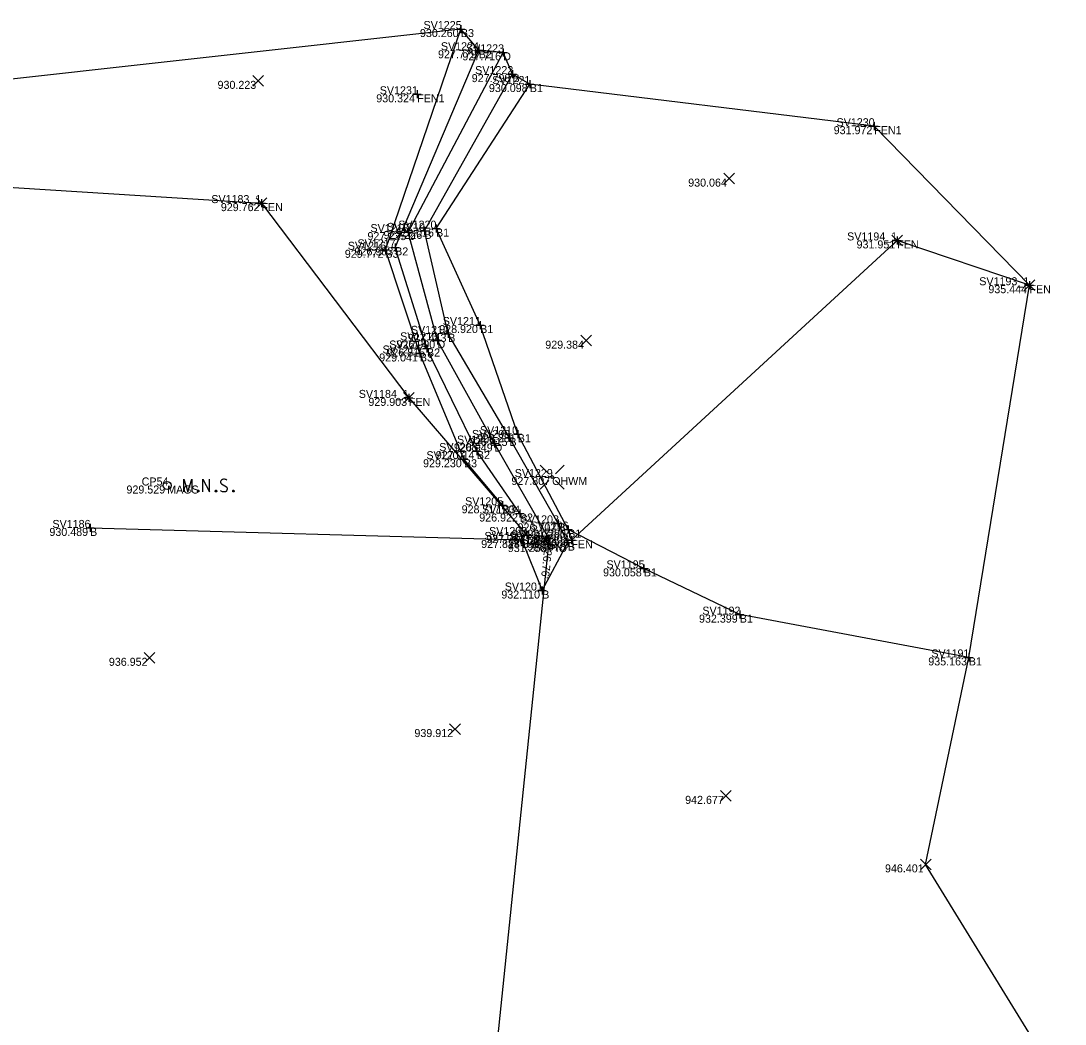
# Model space of a CAD drawing. Extents: x 2065431 to 2068157, y 709104 to 709719.
# Drawn here: x 2067248 to 2067378.4, y 709504.2 to 709629.4 of the extents above; entities that cross this region are included whole.
import ezdxf

# ---------------------------------------------------------------- set-up
doc = ezdxf.new("R2010")
doc.units = 0
for name, color, linetype in [('_CIVIL_CONSTRUCTION', 7, 'Continuous'), ('DR_X_Storm_Sewer', 7, 'Continuous'), ('DT_X_Terrain_Boundary', 7, 'Continuous'), ('RD_X_Fence', 7, 'Continuous'), ('RS_Raster1', 7, 'Continuous'), ('RW_X_CL_100_Bearings', 7, 'Continuous'), ('RW_X_CL_100_Curve_Data', 7, 'Continuous'), ('RW_X_CL_100_Stations', 7, 'Continuous'), ('RW_X_Fee_WL', 7, 'Continuous'), ('SC_Scratch1', 7, 'Continuous'), ('SV_X_Break_Lines', 7, 'Continuous'), ('SV_X_Mon_Cells_Found', 7, 'Continuous'), ('SV_X_Text_Elevation', 7, 'Continuous'), ('SV_X_Text_Name', 7, 'Continuous')]:
    doc.layers.add(name, color=color, linetype=linetype)

msp = doc.modelspace()

# ---------------------------------------------------------------- linework, layer by layer
at = {"layer": '_CIVIL_CONSTRUCTION'}
for p, q in [((2067313.41, 709564.11), (2067314.41, 709564.11)), ((2067313.91, 709564.61), (2067313.91, 709563.61)), ((2067313.91, 709564.11), (2067313.91, 709564.11))]:
    msp.add_line(p, q, dxfattribs=at)
at = {"layer": 'DR_X_Storm_Sewer'}
msp.add_line((2067313.91, 709564.11), (2067272.26, 709162.87), dxfattribs=at)
at = {"layer": 'DT_X_Terrain_Boundary'}
msp.add_lwpolyline([(2067560.73, 709418.79), (2067495.34, 709436.29), (2067456.65, 709439.38), (2067410.67, 709443.42), (2067361.02, 709524.1), (2067366.41, 709549.95), (2067373.99, 709596.43), (2067354.6, 709616.29), (2067311.55, 709621.56), (2067309.4, 709622.8), (2067308.24, 709625.52), (2067305.17, 709625.78), (2067302.95, 709628.43), (2067239.24, 709621.32), (2067197.78, 709611.01), (2067153.08, 709612.99), (2067144.2, 709539.81), (2067080.32, 709510.92)], dxfattribs=at)
at = {"layer": 'RD_X_Fence'}
for points in [[(2067153.08, 709612.99), (2067197.68, 709610.98), (2067232.51, 709609.56), (2067278.02, 709606.69), (2067296.45, 709582.36), (2067311.18, 709565.23)], [(2067373.99, 709596.43), (2067357.47, 709602.03), (2067316.75, 709564.58)]]:
    msp.add_lwpolyline(points, dxfattribs=at)
at = {"layer": 'RS_Raster1'}
for p, q in [((2067302.45, 709628.43), (2067303.45, 709628.43)), ((2067302.95, 709628.93), (2067302.95, 709627.93)), ((2067302.95, 709628.43), (2067302.95, 709628.43)), ((2067304.67, 709625.78), (2067305.67, 709625.78)), ((2067305.17, 709626.28), (2067305.17, 709625.28)), ((2067305.17, 709625.78), (2067305.17, 709625.78)), ((2067307.74, 709625.52), (2067308.74, 709625.52)), ((2067308.24, 709626.02), (2067308.24, 709625.02)), ((2067308.24, 709625.52), (2067308.24, 709625.52)), ((2067308.9, 709622.8), (2067309.9, 709622.8)), ((2067309.4, 709623.3), (2067309.4, 709622.3)), ((2067309.4, 709622.8), (2067309.4, 709622.8)), ((2067311.05, 709621.56), (2067312.05, 709621.56)), ((2067311.55, 709622.06), (2067311.55, 709621.06)), ((2067311.55, 709621.56), (2067311.55, 709621.56)), ((2067296.99, 709620.28), (2067297.99, 709620.28)), ((2067297.49, 709620.78), (2067297.49, 709619.78)), ((2067297.49, 709620.28), (2067297.49, 709620.28)), ((2067354.1, 709616.29), (2067355.1, 709616.29)), ((2067354.6, 709616.79), (2067354.6, 709615.79)), ((2067354.6, 709616.29), (2067354.6, 709616.29)), ((2067278.02, 709607.19), (2067278.02, 709606.19)), ((2067277.52, 709606.69), (2067278.52, 709606.69)), ((2067278.02, 709606.69), (2067278.02, 709606.69)), ((2067295.84, 709603.07), (2067296.84, 709603.07)), ((2067296.34, 709603.57), (2067296.34, 709602.57)), ((2067296.34, 709603.07), (2067296.34, 709603.07)), ((2067297.89, 709603.22), (2067298.89, 709603.22)), ((2067298.39, 709603.72), (2067298.39, 709602.72)), ((2067298.39, 709603.22), (2067298.39, 709603.22)), ((2067299.34, 709603.5), (2067300.34, 709603.5)), ((2067299.84, 709604), (2067299.84, 709603)), ((2067299.84, 709603.5), (2067299.84, 709603.5)), ((2067294.73, 709601.66), (2067294.73, 709600.66)), ((2067356.97, 709602.03), (2067357.97, 709602.03)), ((2067357.47, 709602.53), (2067357.47, 709601.53)), ((2067357.47, 709602.03), (2067357.47, 709602.03)), ((2067293.02, 709600.86), (2067294.02, 709600.86)), ((2067293.52, 709601.36), (2067293.52, 709600.36)), ((2067293.52, 709600.86), (2067293.52, 709600.86)), ((2067294.23, 709601.16), (2067295.23, 709601.16)), ((2067294.73, 709601.16), (2067294.73, 709601.16)), ((2067373.49, 709596.43), (2067374.49, 709596.43)), ((2067373.99, 709596.93), (2067373.99, 709595.93)), ((2067373.99, 709596.43), (2067373.99, 709596.43)), ((2067304.85, 709591.46), (2067305.85, 709591.46)), ((2067305.35, 709591.96), (2067305.35, 709590.96)), ((2067305.35, 709591.46), (2067305.35, 709591.46)), ((2067300.02, 709590.05), (2067300.02, 709589.05)), ((2067300.87, 709590.36), (2067301.87, 709590.36)), ((2067301.37, 709590.86), (2067301.37, 709589.86)), ((2067301.37, 709590.36), (2067301.37, 709590.36)), ((2067298.71, 709589.03), (2067298.71, 709588.03)), ((2067299.52, 709589.55), (2067300.52, 709589.55)), ((2067300.02, 709589.55), (2067300.02, 709589.55)), ((2067297.32, 709587.91), (2067298.32, 709587.91)), ((2067297.82, 709588.41), (2067297.82, 709587.41)), ((2067297.82, 709587.91), (2067297.82, 709587.91)), ((2067298.21, 709588.53), (2067299.21, 709588.53)), ((2067298.71, 709588.53), (2067298.71, 709588.53)), ((2067295.95, 709582.36), (2067296.95, 709582.36)), ((2067296.45, 709582.86), (2067296.45, 709581.86)), ((2067296.45, 709582.36), (2067296.45, 709582.36)), ((2067310.05, 709578.33), (2067310.05, 709577.33)), ((2067307.16, 709577.16), (2067307.16, 709576.16)), ((2067308.51, 709577.36), (2067309.51, 709577.36)), ((2067309.01, 709577.86), (2067309.01, 709576.86)), ((2067309.01, 709577.36), (2067309.01, 709577.36)), ((2067309.55, 709577.83), (2067310.55, 709577.83)), ((2067310.05, 709577.83), (2067310.05, 709577.83)), ((2067304.44, 709575.72), (2067305.44, 709575.72)), ((2067304.94, 709576.22), (2067304.94, 709575.22)), ((2067304.94, 709575.72), (2067304.94, 709575.72)), ((2067306.66, 709576.66), (2067307.66, 709576.66)), ((2067307.16, 709576.66), (2067307.16, 709576.66)), ((2067302.83, 709574.7), (2067303.83, 709574.7)), ((2067303.33, 709575.2), (2067303.33, 709574.2)), ((2067303.33, 709574.7), (2067303.33, 709574.7)), ((2067308.14, 709569.45), (2067308.14, 709568.45)), ((2067307.64, 709568.95), (2067308.64, 709568.95)), ((2067308.14, 709568.95), (2067308.14, 709568.95)), ((2067309.81, 709567.92), (2067310.81, 709567.92)), ((2067310.31, 709568.42), (2067310.31, 709567.42)), ((2067310.31, 709567.92), (2067310.31, 709567.92)), ((2067256.61, 709566.62), (2067256.61, 709565.62)), ((2067314.6, 709566.69), (2067315.6, 709566.69)), ((2067315.1, 709567.19), (2067315.1, 709566.19)), ((2067315.1, 709566.69), (2067315.1, 709566.69)), ((2067316.35, 709566.41), (2067316.35, 709565.41)), ((2067256.11, 709566.12), (2067257.11, 709566.12)), ((2067256.61, 709566.12), (2067256.61, 709566.12)), ((2067310.58, 709565.12), (2067310.58, 709564.12)), ((2067310.68, 709565.23), (2067311.68, 709565.23)), ((2067311.18, 709565.73), (2067311.18, 709564.73)), ((2067311.18, 709565.23), (2067311.18, 709565.23)), ((2067313.95, 709565.3), (2067313.95, 709564.3)), ((2067315.85, 709565.91), (2067316.85, 709565.91)), ((2067316.35, 709565.91), (2067316.35, 709565.91)), ((2067316.75, 709565.08), (2067316.75, 709564.08)), ((2067310.08, 709564.62), (2067311.08, 709564.62)), ((2067310.58, 709564.62), (2067310.58, 709564.62)), ((2067313.45, 709564.8), (2067314.45, 709564.8)), ((2067313.95, 709564.8), (2067313.95, 709564.8)), ((2067315.82, 709564.29), (2067316.82, 709564.29)), ((2067316.25, 709564.58), (2067317.25, 709564.58)), ((2067316.32, 709564.79), (2067316.32, 709563.79)), ((2067316.32, 709564.29), (2067316.32, 709564.29)), ((2067316.75, 709564.58), (2067316.75, 709564.58)), ((2067325.81, 709561.57), (2067325.81, 709560.57)), ((2067325.31, 709561.07), (2067326.31, 709561.07)), ((2067325.81, 709561.07), (2067325.81, 709561.07)), ((2067313.11, 709558.8), (2067313.11, 709557.8)), ((2067312.61, 709558.3), (2067313.61, 709558.3)), ((2067313.11, 709558.3), (2067313.11, 709558.3)), ((2067337.29, 709555.29), (2067338.29, 709555.29)), ((2067337.79, 709555.79), (2067337.79, 709554.79)), ((2067337.79, 709555.29), (2067337.79, 709555.29)), ((2067365.91, 709549.95), (2067366.91, 709549.95)), ((2067366.41, 709550.45), (2067366.41, 709549.45)), ((2067366.41, 709549.95), (2067366.41, 709549.95))]:
    msp.add_line(p, q, dxfattribs=at)
at = {"layer": 'RW_X_CL_100_Bearings'}
for p, q in [((2067276.94, 709621.3), (2067278.27, 709622.63)), ((2067276.94, 709622.63), (2067278.27, 709621.3)), ((2067335.81, 709609.08), (2067337.14, 709610.42)), ((2067335.81, 709610.42), (2067337.14, 709609.08)), ((2067277.36, 709606.03), (2067278.69, 709607.36)), ((2067277.36, 709607.36), (2067278.69, 709606.03)), ((2067356.81, 709601.36), (2067358.14, 709602.69)), ((2067356.81, 709602.69), (2067358.14, 709601.36)), ((2067373.32, 709595.77), (2067374.65, 709597.1)), ((2067373.32, 709597.1), (2067374.65, 709595.77)), ((2067317.94, 709588.85), (2067319.27, 709590.18)), ((2067317.94, 709590.18), (2067319.27, 709588.85)), ((2067295.78, 709581.69), (2067297.12, 709583.03)), ((2067295.78, 709583.03), (2067297.12, 709581.69)), ((2067263.36, 709549.23), (2067264.7, 709550.56)), ((2067263.36, 709550.56), (2067264.7, 709549.23)), ((2067301.54, 709540.33), (2067302.88, 709541.67)), ((2067301.54, 709541.67), (2067302.88, 709540.33)), ((2067335.4, 709531.99), (2067336.73, 709533.33)), ((2067335.4, 709533.33), (2067336.73, 709531.99)), ((2067360.36, 709523.43), (2067361.69, 709524.77)), ((2067360.36, 709524.77), (2067361.69, 709523.43))]:
    msp.add_line(p, q, dxfattribs=at)
at = {"layer": 'RW_X_CL_100_Curve_Data'}
for points in [[(2067268.34, 709570.62), (2067268.34, 709572.22), (2067268.84, 709570.62), (2067269.33, 709572.22), (2067269.33, 709570.62)], [(2067270.71, 709570.62), (2067270.71, 709572.22), (2067271.53, 709570.62), (2067271.53, 709572.22)], [(2067273.68, 709572.1), (2067273.66, 709572.13), (2067273.63, 709572.15), (2067273.53, 709572.19), (2067273.41, 709572.22), (2067273.32, 709572.22), (2067273.29, 709572.22), (2067273.14, 709572.18), (2067273.02, 709572.1), (2067272.94, 709572), (2067272.92, 709571.9), (2067272.92, 709571.83), (2067272.94, 709571.73), (2067273.03, 709571.64), (2067273.64, 709571.26), (2067273.69, 709571.21), (2067273.72, 709571.16), (2067273.74, 709571.08), (2067273.74, 709571.01), (2067273.73, 709570.93), (2067273.72, 709570.88), (2067273.69, 709570.82), (2067273.67, 709570.77), (2067273.65, 709570.73), (2067273.62, 709570.69), (2067273.58, 709570.67), (2067273.54, 709570.64), (2067273.51, 709570.63), (2067273.41, 709570.62), (2067273.25, 709570.62), (2067273.15, 709570.64), (2067273.01, 709570.73), (2067272.92, 709570.81)], [(2067270.1, 709570.83), (2067270.16, 709570.83), (2067270.19, 709570.81), (2067270.22, 709570.76), (2067270.22, 709570.69), (2067270.19, 709570.64), (2067270.16, 709570.62), (2067270.1, 709570.62), (2067270.07, 709570.64), (2067270.04, 709570.69), (2067270.04, 709570.76), (2067270.07, 709570.81), (2067270.1, 709570.83)], [(2067272.32, 709570.83), (2067272.37, 709570.83), (2067272.4, 709570.81), (2067272.44, 709570.76), (2067272.44, 709570.69), (2067272.4, 709570.64), (2067272.37, 709570.62), (2067272.32, 709570.62), (2067272.28, 709570.64), (2067272.25, 709570.69), (2067272.25, 709570.76), (2067272.28, 709570.81), (2067272.32, 709570.83)], [(2067274.5, 709570.83), (2067274.55, 709570.83), (2067274.59, 709570.81), (2067274.62, 709570.76), (2067274.62, 709570.69), (2067274.59, 709570.64), (2067274.55, 709570.62), (2067274.5, 709570.62), (2067274.47, 709570.64), (2067274.43, 709570.69), (2067274.43, 709570.76), (2067274.47, 709570.81), (2067274.5, 709570.83)]]:
    msp.add_lwpolyline(points, dxfattribs=at)
msp.add_circle((2067266.25, 709571.42), 0.497, dxfattribs=at)
at = {"layer": 'RW_X_CL_100_Stations'}
for p, q in [((2067312.84, 709573.98), (2067313.94, 709572.89)), ((2067314.77, 709572.89), (2067315.86, 709573.98)), ((2067312.84, 709570.96), (2067313.94, 709572.06)), ((2067314.77, 709572.06), (2067315.86, 709570.96))]:
    msp.add_line(p, q, dxfattribs=at)
msp.add_circle((2067314.35, 709572.48), 0.17, dxfattribs=at)
at = {"layer": 'RW_X_Fee_WL'}
msp.add_lwpolyline([(2067313.95, 709564.8), (2067307.16, 709576.66), (2067300.02, 709589.55), (2067296.34, 709603.07), (2067308.24, 709625.52)], dxfattribs=at)
at = {"layer": 'SV_X_Break_Lines'}
for points in [[(2067308.14, 709568.95), (2067303.33, 709574.7), (2067297.82, 709587.91), (2067293.52, 709600.86), (2067302.95, 709628.43)], [(2067310.31, 709567.92), (2067304.94, 709575.72), (2067298.71, 709588.53), (2067294.73, 709601.16), (2067305.17, 709625.78)], [(2067256.61, 709566.12), (2067310.58, 709564.62), (2067313.11, 709558.3), (2067316.32, 709564.29), (2067315.1, 709566.69), (2067309.01, 709577.36), (2067301.37, 709590.36), (2067298.39, 709603.22), (2067309.4, 709622.8)], [(2067366.41, 709549.95), (2067337.79, 709555.29), (2067325.81, 709561.07), (2067316.35, 709565.91), (2067310.05, 709577.83), (2067305.35, 709591.46), (2067299.84, 709603.5), (2067311.55, 709621.56)]]:
    msp.add_lwpolyline(points, dxfattribs=at)

# ---------------------------------------------------------------- texts
at = {"layer": 'SC_Scratch1'}
msp.add_text("926.76'", height=1, rotation=264.0747, dxfattribs=at).set_placement((2067313.41, 709564.16))
at = {"layer": 'SV_X_Mon_Cells_Found'}
for s, p in [('SV1225', (2067298.28, 709628.43)), ('SV1224', (2067300.45, 709625.78)), ('SV1223', (2067303.58, 709625.52)), ('SV1222', (2067304.73, 709622.8)), ('SV1221', (2067306.87, 709621.56)), ('SV1231', (2067292.81, 709620.28)), ('SV1230', (2067349.89, 709616.29)), ('SV1183_1', (2067271.76, 709606.69)), ('SV1219', (2067293.71, 709603.22)), ('SV1220', (2067295.13, 709603.5)), ('SV1218', (2067291.65, 709603.07)), ('SV1194_1', (2067351.21, 709602.03)), ('SV1216', (2067288.82, 709600.86)), ('SV1217', (2067290.03, 709601.16)), ('SV1193_1', (2067367.72, 709596.43)), ('SV1211', (2067300.68, 709591.46)), ('SV1212', (2067296.7, 709590.36)), ('SV1213', (2067295.36, 709589.55)), ('SV1215', (2067293.16, 709587.91)), ('SV1214', (2067293.99, 709588.53)), ('SV1184_1', (2067290.19, 709582.36)), ('SV1209', (2067304.33, 709577.36)), ('SV1210', (2067305.33, 709577.83)), ('SV1206', (2067302.46, 709576.66)), ('SV1207', (2067298.64, 709574.7)), ('SV1208', (2067300.24, 709575.72)), ('SV1229', (2067309.67, 709572.48)), ('CP54', (2067263.06, 709571.42)), ('SV1205', (2067303.47, 709568.95)), ('SV1204', (2067305.59, 709567.92)), ('SV1203', (2067310.44, 709566.69)), ('SV1186', (2067251.91, 709566.12)), ('SV1196', (2067311.65, 709565.91)), ('SV1199', (2067305.89, 709564.62)), ('SV1200', (2067306.47, 709565.23)), ('SV1198', (2067309.21, 709564.11)), ('SV1197', (2067309.26, 709564.8)), ('SV1202', (2067311.65, 709564.29)), ('SV7000', (2067312.03, 709564.58)), ('SV1195', (2067321.14, 709561.07)), ('SV1201', (2067308.43, 709558.3)), ('SV1192', (2067333.12, 709555.29)), ('SV1191', (2067361.73, 709549.95))]:
    msp.add_text(s, height=1, dxfattribs=at).set_placement(p)
at = {"layer": 'SV_X_Text_Elevation'}
for s, p in [('B3', (2067302.95, 709627.43)), ('B2', (2067305.17, 709624.78)), ('D', (2067308.24, 709624.52)), ('B', (2067309.4, 709621.8)), ('B1', (2067311.55, 709620.56)), ('FEN1', (2067297.49, 709619.28)), ('FEN1', (2067354.6, 709615.3)), ('FEN', (2067278.02, 709605.69)), ('D', (2067296.34, 709602.07)), ('B', (2067298.39, 709602.22)), ('B1', (2067299.84, 709602.5)), ('FEN', (2067357.47, 709601.03)), ('B3', (2067293.52, 709599.86)), ('B2', (2067294.73, 709600.16)), ('FEN', (2067373.99, 709595.44)), ('B1', (2067305.35, 709590.46)), ('B', (2067301.37, 709589.36)), ('B2', (2067298.71, 709587.53)), ('D', (2067300.02, 709588.55)), ('B3', (2067297.82, 709586.91)), ('FEN', (2067296.45, 709581.36)), ('B', (2067309.01, 709576.36)), ('B1', (2067310.05, 709576.83)), ('B2', (2067304.94, 709574.72)), ('D', (2067307.16, 709575.66)), ('B3', (2067303.33, 709573.7)), ('OHWM', (2067314.35, 709571.48)), ('MAGS', (2067266.25, 709570.42)), ('B3', (2067308.14, 709567.95)), ('B2', (2067310.31, 709566.92)), ('B', (2067315.1, 709565.69)), ('B', (2067256.61, 709565.12)), ('FEN', (2067311.18, 709564.23)), ('B1', (2067316.35, 709564.91)), ('B', (2067310.58, 709563.62)), ('PIO', (2067313.91, 709563.11)), ('D', (2067313.95, 709563.8)), ('B', (2067316.32, 709563.29)), ('FEN', (2067316.75, 709563.58)), ('B1', (2067325.81, 709560.07)), ('B', (2067313.11, 709557.3)), ('B1', (2067337.79, 709554.29)), ('B1', (2067366.41, 709548.95))]:
    msp.add_text(s, height=1, dxfattribs=at).set_placement(p)
at = {"layer": 'SV_X_Text_Name'}
for s, p in [('930.260', (2067297.83, 709627.43)), ('927.779', (2067300.09, 709624.78)), ('927.716', (2067303.13, 709624.52)), ('927.798', (2067304.3, 709621.8)), ('930.223', (2067272.54, 709620.96)), ('930.098', (2067306.45, 709620.56)), ('930.324', (2067292.37, 709619.28)), ('931.972', (2067349.53, 709615.3)), ('930.064', (2067331.35, 709608.75)), ('929.762', (2067272.95, 709605.69)), ('929.762', (2067272.95, 709605.69)), ('927.225', (2067291.27, 709602.07)), ('927.226', (2067293.28, 709602.22)), ('929.016', (2067294.74, 709602.5)), ('931.951', (2067352.39, 709601.03)), ('931.951', (2067352.39, 709601.03)), ('929.772', (2067288.44, 709599.86)), ('926.983', (2067289.66, 709600.16)), ('935.444', (2067368.86, 709595.44)), ('935.444', (2067368.86, 709595.44)), ('928.920', (2067300.24, 709590.46)), ('927.443', (2067296.31, 709589.36)), ('926.815', (2067293.64, 709587.53)), ('926.900', (2067294.9, 709588.55)), ('929.384', (2067313.49, 709588.51)), ('929.041', (2067292.74, 709586.91)), ('929.903', (2067291.39, 709581.36)), ('929.903', (2067291.39, 709581.36)), ('926.915', (2067303.94, 709576.36)), ('928.281', (2067304.96, 709576.83)), ('927.014', (2067299.81, 709574.72)), ('926.949', (2067302.08, 709575.66)), ('929.230', (2067298.22, 709573.7)), ('927.807', (2067309.26, 709571.48)), ('929.529', (2067261.16, 709570.42)), ('928.717', (2067303.04, 709567.95)), ('926.922', (2067305.24, 709566.92)), ('926.702', (2067310.03, 709565.69)), ('930.489', (2067251.53, 709565.12)), ('927.763', (2067306.12, 709564.23)), ('927.290', (2067311.24, 709564.91)), ('927.818', (2067305.48, 709563.62)), ('931.258', (2067308.81, 709563.11)), ('926.444', (2067308.83, 709563.8)), ('928.078', (2067311.22, 709563.29)), ('929.000', (2067311.63, 709563.58)), ('930.058', (2067320.71, 709560.07)), ('932.110', (2067308, 709557.3)), ('932.399', (2067332.7, 709554.29)), ('936.952', (2067258.96, 709548.9)), ('935.163', (2067361.35, 709548.95)), ('939.912', (2067297.14, 709540)), ('942.677', (2067330.97, 709531.66)), ('946.401', (2067355.94, 709523.1))]:
    msp.add_text(s, height=1, dxfattribs=at).set_placement(p)

doc.saveas('drawing.dxf')
